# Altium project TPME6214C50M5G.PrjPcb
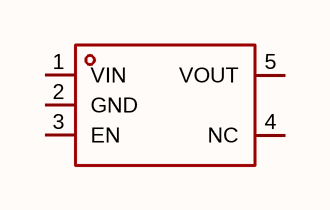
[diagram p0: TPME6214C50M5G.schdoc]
1 sheet, 1 parts. Net scope: global (net labels, ports and power ports of the same name join across sheets).

## Sheet TPME6214C50M5G.schdoc
size 127 x 101 mm

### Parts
U?  tpme6214c50m5g  [SOT-23-5_L2.9-W1.6-P0.95-LS2.8-BR]  (value not drawn)

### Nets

Not connected (* = marked no-connect by the designer): U? 1(VIN) 2(GND) 3(EN) 4(NC) 5(VOUT)

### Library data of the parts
U? = tpme6214c50m5g: 输出极性:正极;工作电压:18V;输出电压:5V;输出电流:300mA;电源纹波抑制比(PSRR):70dB@(1kHz);输出类型:固定;; Manufacturer: TECH PUBLIC(台舟); AddInBom: yes; ModelId: 7ba65df16e7b4570af156e925f9c37fe; ModelTransform: 114.173,114.173,0,90,0,0,0,0,0; Output Configuration: 正极; Voltage - Supply: 18V; Output Voltage: 5V; Output Current: 300mA; Voltage Dropout: 120mV@(100mA); standby current: 1.5uA; Output Type: 固定; Number of Outputs: 1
